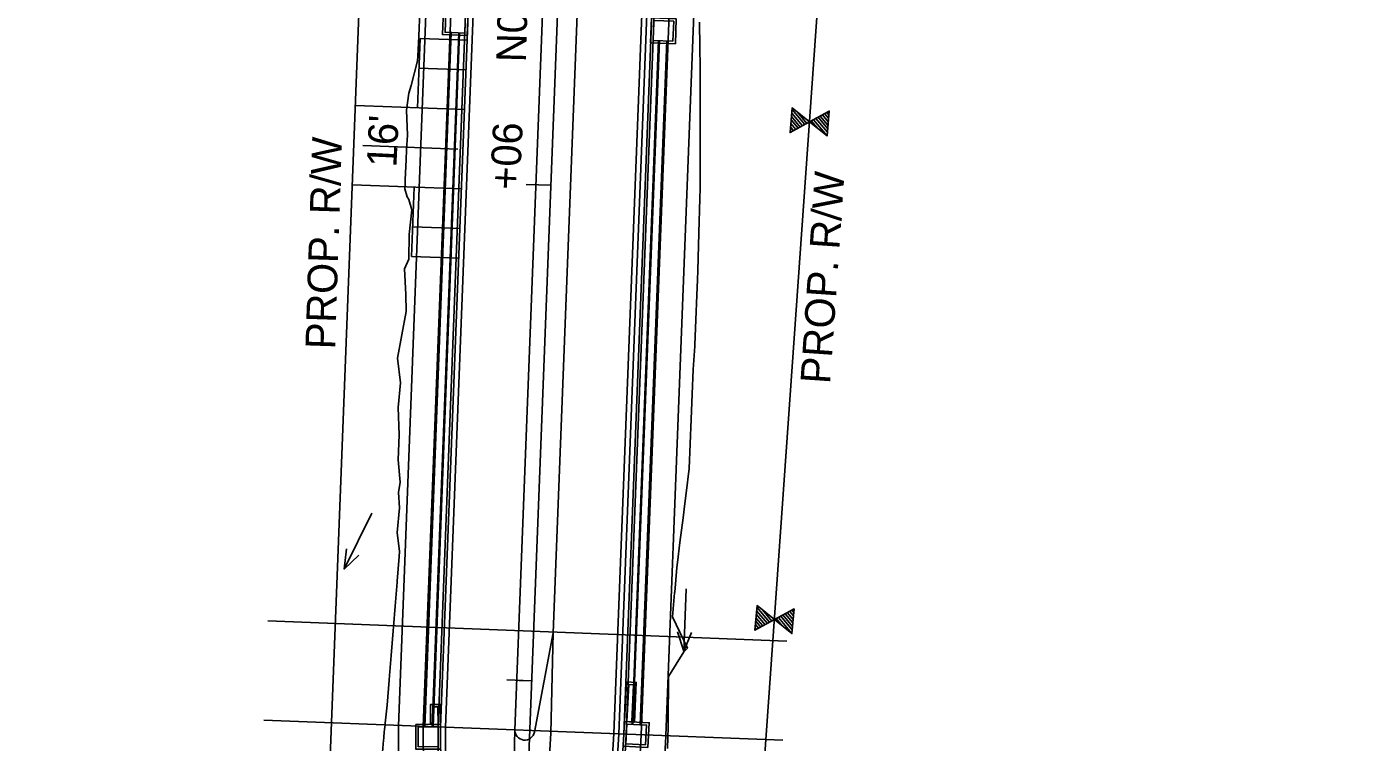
# Model space of a CAD drawing. Extents: x 670017 to 673226, y 705371 to 707498.
# Drawn here: x 671611 to 671881.1, y 706169.7 to 706314 of the extents above; entities that cross this region are included whole.
import ezdxf

# ---------------------------------------------------------------- set-up
doc = ezdxf.new("R2010")
doc.units = 0
for name, color, linetype in [('EL L SCBV', 7, 'Continuous'), ('EL R SCBV', 7, 'Continuous'), ('R_Drainage Flow Lines', 7, 'Continuous'), ('R_Drainage Stage 1A', 7, 'Continuous'), ('R_Drainage Stage 2', 7, 'Continuous'), ('R_Drainage Stage 2A', 7, 'Continuous'), ('R_Drive Annot Stage 2A', 7, 'Continuous'), ('R_Drive Stage 2A', 7, 'Continuous'), ('R_Fence', 7, 'Continuous'), ('R_Horz Alg', 7, 'Continuous'), ('R_Horz Alg Station', 7, 'Continuous'), ('R_Horz Bearing', 7, 'Continuous'), ('R_No Plot', 7, 'Continuous'), ('R_No Plot FOC', 7, 'Continuous'), ('R_Proposed Const Limits Stage 2', 7, 'Continuous'), ('R_Proposed Const Limits Stage 2A', 7, 'Continuous'), ('R_Proposed Median', 7, 'Continuous'), ('R_Proposed Road Stage 2', 7, 'Continuous'), ('R_Proposed Road Stage 2A', 7, 'Continuous'), ('R_Proposed Sidewalk Stage 2', 7, 'Continuous'), ('R_Proposed Sidewalk Stage 2A', 7, 'Continuous'), ('R_ROW', 7, 'Continuous'), ('R_ROW Annot', 7, 'Continuous'), ('R_Striping', 7, 'Continuous'), ('R_Water Annot', 7, 'Continuous')]:
    doc.layers.add(name, color=color, linetype=linetype)

# ---------------------------------------------------------------- blocks, each defined once
blk = doc.blocks.new('FLOW ARROW')
at = {"layer": 'R_Water Annot'}
for p, q in [((-12.57, 0), (0, 0)), ((0, 0), (-3.85, 1.4)), ((0, 0), (-3.85, -1.4))]:
    blk.add_line(p, q, dxfattribs=at)

msp = doc.modelspace()

# ---------------------------------------------------------------- linework, layer by layer
at = {"layer": 'EL L SCBV'}
for p, q in [((671700.83, 706337.88), (671694.44, 706172.8)), ((671694.44, 706172.8), (671696.1, 706017.44))]:
    msp.add_line(p, q, dxfattribs=at)
at = {"layer": 'EL R SCBV'}
for p, q in [((671737.48, 706379.84), (671729.41, 706171.45)), ((671729.41, 706171.45), (671727.09, 706134.51))]:
    msp.add_line(p, q, dxfattribs=at)
at = {"layer": 'R_Drainage Stage 1A'}
for points in [[(671731.54, 706173.88), (671731.92, 706181.87), (671733.92, 706181.78), (671733.54, 706173.79)], [(671732.04, 706173.86), (671732.39, 706181.35), (671733.39, 706181.3), (671733.04, 706173.81)]]:
    msp.add_lwpolyline(points, close=True, dxfattribs=at)
at = {"layer": 'R_Drainage Stage 2'}
for p, q in [((671738.41, 706311.2), (671733.07, 706173.31)), ((671738.58, 706311.2), (671733.24, 706173.3)), ((671740.08, 706311.14), (671734.74, 706173.22)), ((671740.24, 706311.13), (671734.9, 706173.21))]:
    msp.add_line(p, q, dxfattribs=at)
for points in [[(671741.81, 706310.57), (671742, 706315.57), (671737, 706315.76), (671736.81, 706310.76)], [(671741.33, 706311.09), (671741.48, 706315.09), (671737.48, 706315.24), (671737.33, 706311.24)], [(671736.28, 706168.64), (671736.53, 706173.63), (671731.54, 706173.88), (671731.29, 706168.89)], [(671735.81, 706169.16), (671736.01, 706173.16), (671732.01, 706173.36), (671731.81, 706169.36)]]:
    msp.add_lwpolyline(points, close=True, dxfattribs=at)
at = {"layer": 'R_Drainage Stage 2A'}
for p, q in [((671696.44, 706312.83), (671691.11, 706172.81)), ((671696.61, 706312.82), (671691.28, 706172.81)), ((671698.11, 706312.76), (671692.78, 706172.82)), ((671698.28, 706312.76), (671692.95, 706172.82))]:
    msp.add_line(p, q, dxfattribs=at)
for points in [[(671695.04, 706317.39), (671694.84, 706312.39), (671699.84, 706312.2), (671700.03, 706317.19)], [(671695.52, 706316.87), (671695.36, 706312.87), (671699.36, 706312.71), (671699.51, 706316.71)], [(671692.44, 706173.32), (671692.42, 706177.32), (671694.42, 706177.33), (671694.44, 706173.33)], [(671692.94, 706173.32), (671692.92, 706176.82), (671693.92, 706176.82), (671693.94, 706173.32)], [(671689.44, 706173.3), (671689.47, 706168.3), (671694.46, 706168.33), (671694.44, 706173.33)], [(671689.94, 706172.8), (671689.96, 706168.8), (671693.96, 706168.82), (671693.94, 706172.82)]]:
    msp.add_lwpolyline(points, close=True, dxfattribs=at)
at = {"layer": 'R_Drive Stage 2A'}
for p, q in [((671689.77, 706297.64), (671690.31, 706311.63)), ((671690.31, 706311.63), (671699.8, 706311.26)), ((671690.08, 706305.63), (671699.57, 706305.27)), ((671677.28, 706298.12), (671699.26, 706297.27)), ((671676.66, 706282.14), (671698.64, 706281.28)), ((671689.15, 706281.65), (671688.61, 706267.66)), ((671688.84, 706273.66), (671698.33, 706273.29)), ((671688.61, 706267.66), (671698.1, 706267.3))]:
    msp.add_line(p, q, dxfattribs=at)
at = {"layer": 'R_Fence'}
for p, q in [((671765.28, 706296.59), (671767.45, 706294.01)), ((671765.34, 706297.3), (671767.89, 706294.26)), ((671766.46, 706296.74), (671768.34, 706294.5)), ((671771.92, 706296.46), (671772.71, 706295.52)), ((671772.36, 706296.71), (671772.77, 706296.22)), ((671772.81, 706296.95), (671772.83, 706296.93)), ((671765.03, 706293.78), (671765.66, 706293.03)), ((671765.09, 706294.48), (671766.1, 706293.28)), ((671765.15, 706295.19), (671766.55, 706293.52)), ((671765.21, 706295.89), (671767, 706293.77)), ((671768.45, 706295.14), (671768.79, 706294.75)), ((671769.23, 706294.99), (671770.45, 706293.55)), ((671769.68, 706295.24), (671772.41, 706292)), ((671770.13, 706295.48), (671772.47, 706292.7)), ((671770.58, 706295.73), (671772.53, 706293.41)), ((671771.02, 706295.97), (671772.59, 706294.11)), ((671771.47, 706296.22), (671772.65, 706294.81)), ((671764.97, 706293.07), (671765.21, 706292.79)), ((671758.26, 706196.95), (671760.81, 706193.9)), ((671765.73, 706196.6), (671765.75, 706196.57)), ((671758.01, 706194.13), (671759.03, 706192.92)), ((671758.07, 706194.83), (671759.47, 706193.17)), ((671758.13, 706195.54), (671759.92, 706193.41)), ((671758.2, 706196.24), (671760.37, 706193.66)), ((671759.38, 706196.38), (671761.26, 706194.15)), ((671761.37, 706194.79), (671761.71, 706194.39)), ((671762.16, 706194.64), (671763.37, 706193.2)), ((671762.6, 706194.88), (671765.33, 706191.64)), ((671763.05, 706195.13), (671765.39, 706192.35)), ((671763.5, 706195.37), (671765.45, 706193.05)), ((671763.94, 706195.62), (671765.51, 706193.76)), ((671764.39, 706195.86), (671765.57, 706194.46)), ((671764.84, 706196.11), (671765.63, 706195.17)), ((671765.28, 706196.35), (671765.69, 706195.87)), ((671757.89, 706192.72), (671758.13, 706192.43)), ((671757.95, 706193.42), (671758.58, 706192.68))]:
    msp.add_line(p, q, dxfattribs=at)
for points in [[(671768.89, 706294.8), (671768.88, 706294.81), (671765.36, 706297.61), (671764.93, 706292.63), (671768.88, 706294.8), (671768.89, 706294.79), (671772.4, 706291.99), (671772.84, 706296.97), (671768.89, 706294.8)], [(671761.81, 706194.45), (671761.8, 706194.45), (671758.28, 706197.26), (671757.85, 706192.28), (671761.8, 706194.44), (671761.81, 706194.44), (671765.32, 706191.63), (671765.76, 706196.61), (671761.81, 706194.45)]]:
    msp.add_lwpolyline(points, dxfattribs=at)
at = {"layer": 'R_Horz Alg'}
msp.add_line((671681.86, 705382.69), (671726.73, 706541.35), dxfattribs=at)
at = {"layer": 'R_Horz Alg Station'}
for points in [[(671711.69, 706282.21), (671716.68, 706282.02)], [(671714.19, 706282.12), (671716.68, 706282.02)], [(671707.82, 706182.29), (671712.81, 706182.1)], [(671710.32, 706182.19), (671712.81, 706182.1)]]:
    msp.add_lwpolyline(points, dxfattribs=at)
at = {"layer": 'R_No Plot'}
msp.add_line((671678.78, 706290.06), (671697.95, 706289.32), dxfattribs=at)
for points in [[(671659.59, 706194.16), (671764.27, 706190.11)], [(671658.81, 706174.18), (671763.5, 706170.13)]]:
    msp.add_lwpolyline(points, dxfattribs=at)
at = {"layer": 'R_No Plot FOC'}
for p, q in [((671731.41, 706171.36), (671739.55, 706381.55)), ((671694.44, 706172.8), (671700.74, 706335.57)), ((671695.1, 706017.42), (671694.44, 706172.8)), ((671722.03, 706006.59), (671731.41, 706171.37))]:
    msp.add_line(p, q, dxfattribs=at)
at = {"layer": 'R_Proposed Const Limits Stage 2'}
for points in [[(671741.26, 706195.01), (671741.66, 706199.82), (671741.67, 706199.99), (671742.11, 706204.98), (671742.21, 706205.98), (671742.72, 706209.96), (671743.36, 706214.94), (671743.72, 706217.84), (671743.98, 706219.92), (671744.57, 706224.9), (671744.79, 706229.89), (671745, 706234.89), (671745.2, 706239.89), (671745.38, 706244.88), (671745.71, 706249.6), (671745.73, 706249.87), (671745.97, 706254.87), (671746.15, 706259.86), (671746.26, 706262.95), (671746.32, 706264.86), (671746.48, 706269.86), (671746.63, 706274.86), (671746.68, 706276.88), (671746.7, 706277.41), (671746.74, 706278.98), (671746.76, 706279.86), (671746.79, 706280.86), (671746.83, 706284.86), (671746.83, 706286.86), (671746.84, 706289.86), (671746.84, 706294.86), (671746.83, 706298.34), (671746.82, 706299.87), (671746.79, 706304.87), (671746.78, 706305.87), (671746.74, 706309.88), (671746.7, 706314.88)], [(671740.43, 706182.95), (671743.5, 706187.95), (671744.23, 706188.71), (671741.26, 706195.01)], [(671740.23, 706168.45), (671740.35, 706172.72), (671740.39, 706177.83), (671740.4, 706178.86), (671740.43, 706182.95)]]:
    msp.add_lwpolyline(points, dxfattribs=at)
at = {"layer": 'R_Proposed Const Limits Stage 2A'}
for points in [[(671685.74, 706247.19), (671687.5, 706256.57), (671687.46, 706260), (671687.2, 706265.16), (671688.02, 706267.09), (671688.09, 706272.09), (671688.69, 706277.1), (671688.03, 706279.15), (671687.7, 706279.69), (671687.24, 706281.28), (671687.28, 706282.16), (671687.33, 706283.16), (671687.52, 706287.15), (671687.61, 706289.15), (671687.75, 706292.15), (671687.61, 706297.16), (671688.04, 706300.62), (671688.53, 706302.13), (671689.82, 706307.08), (671689.88, 706308.08), (671690.04, 706312.07), (671690.24, 706317.07)], [(671686.1, 706231.68), (671685.93, 706237.18), (671686.36, 706242.16), (671685.74, 706247.19)], [(671682.73, 706167.7), (671682.95, 706170.11), (671682.99, 706170.56), (671683, 706170.71), (671683.09, 706171.71), (671683.14, 706172.26), (671683.27, 706173.23), (671683.31, 706173.55), (671683.69, 706177.22), (671684.09, 706182.21), (671684.18, 706183.2), (671684.5, 706187.2), (671684.9, 706192.18), (671684.96, 706192.96), (671685.3, 706197.17), (671685.69, 706201.99), (671685.71, 706202.16), (671686.11, 706207.15), (671686.19, 706208.15), (671685.72, 706212), (671686.18, 706216.99), (671686, 706220.06), (671686.27, 706222.14), (671685.88, 706226.68), (671686.1, 706231.68)]]:
    msp.add_lwpolyline(points, dxfattribs=at)
at = {"layer": 'R_Proposed Median'}
for p, q in [((671717.19, 706191.78), (671725.28, 706400.74)), ((671709.43, 706172.22), (671716.6, 706357.48)), ((671713.39, 706171.77), (671717.19, 706191.78))]:
    msp.add_line(p, q, dxfattribs=at)
msp.add_arc((671711.43, 706172.14), 2, 177.7825, 349.2517, dxfattribs=at)
at = {"layer": 'R_Proposed Road Stage 2'}
for p, q in [((671730.41, 706171.41), (671738.55, 706381.58)), ((671731.91, 706171.35), (671740.05, 706381.53)), ((671721.03, 706006.65), (671730.41, 706171.42)), ((671722.53, 706006.56), (671731.91, 706171.35))]:
    msp.add_line(p, q, dxfattribs=at)
at = {"layer": 'R_Proposed Road Stage 2A'}
for p, q in [((671693.94, 706172.82), (671700.24, 706335.59)), ((671695.44, 706172.76), (671701.74, 706335.54)), ((671694.6, 706017.42), (671693.94, 706172.82)), ((671696.1, 706017.44), (671695.44, 706172.76))]:
    msp.add_line(p, q, dxfattribs=at)
at = {"layer": 'R_Proposed Sidewalk Stage 2'}
for p, q in [((671734.91, 706171.23), (671743.05, 706381.41)), ((671739.91, 706171.04), (671748.05, 706381.22)), ((671725.52, 706006.39), (671734.91, 706171.18)), ((671730.52, 706006.11), (671739.9, 706170.9))]:
    msp.add_line(p, q, dxfattribs=at)
at = {"layer": 'R_Proposed Sidewalk Stage 2A'}
for p, q in [((671685.94, 706172.96), (671692.25, 706335.9)), ((671690.94, 706172.87), (671697.25, 706335.71)), ((671686.64, 706007.99), (671685.94, 706172.96)), ((671691.64, 706009.43), (671690.94, 706172.87))]:
    msp.add_line(p, q, dxfattribs=at)
at = {"layer": 'R_ROW'}
for points in [[(670759.59, 706562.46), (670811.11, 706494.67), (670891, 706490.47), (670958.53, 706537), (671303.32, 706523.91), (671422.37, 706502.64), (671542.46, 706501.35), (671626.3, 706476.92), (671666.37, 706404.06), (671678.47, 706328.82), (671669.08, 706086.55), (671607.47, 706046.07), (671609.57, 705970.93), (671668.36, 705938.63)], [(672596.28, 706451.05), (672596.28, 706451.05), (672161.7, 706463.84), (671891.46, 706473.02), (671825.24, 706451.46), (671776.29, 706399.8), (671754.1, 706085.43), (671832.11, 706032.37), (671817.47, 705912.84), (671726.19, 705881.35)]]:
    msp.add_lwpolyline(points, dxfattribs=at)
at = {"layer": 'R_Striping'}
for p, q in [((671716.72, 706171.57), (671717.19, 706191.78)), ((671709.43, 706172.22), (671706.04, 706007.23)), ((671706.04, 706007.23), (671716.72, 706171.57))]:
    msp.add_line(p, q, dxfattribs=at)

# ---------------------------------------------------------------- block references
at = {"layer": 'R_Drainage Flow Lines'}
for p, rotation in [((671675.01, 706204.64), -116.5183132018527), ((671743.51, 706188.06), -92.21751391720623)]:
    msp.add_blockref('FLOW ARROW', p, dxfattribs=dict(at, rotation=rotation))

# ---------------------------------------------------------------- texts
at = {"layer": 'R_Drive Annot Stage 2A'}
for s, p in [("16'", (671685.53, 706285.56)), ('+06', (671710.38, 706280.98))]:
    msp.add_text(s, height=6, rotation=87.16, dxfattribs=at).set_placement(p)
at = {"layer": 'R_Horz Bearing'}
msp.add_text('N02%%d13\'03"E', height=6, rotation=88.4794, dxfattribs=at).set_placement((671711.68, 706306.78))
at = {"layer": 'R_ROW Annot'}
for rotation, p in [(88.1387, (671673.18, 706248.89)), (86.0885, (671773.01, 706241.85))]:
    msp.add_text('PROP. R/W', height=6, rotation=rotation, dxfattribs=at).set_placement(p)

doc.saveas('drawing.dxf')
